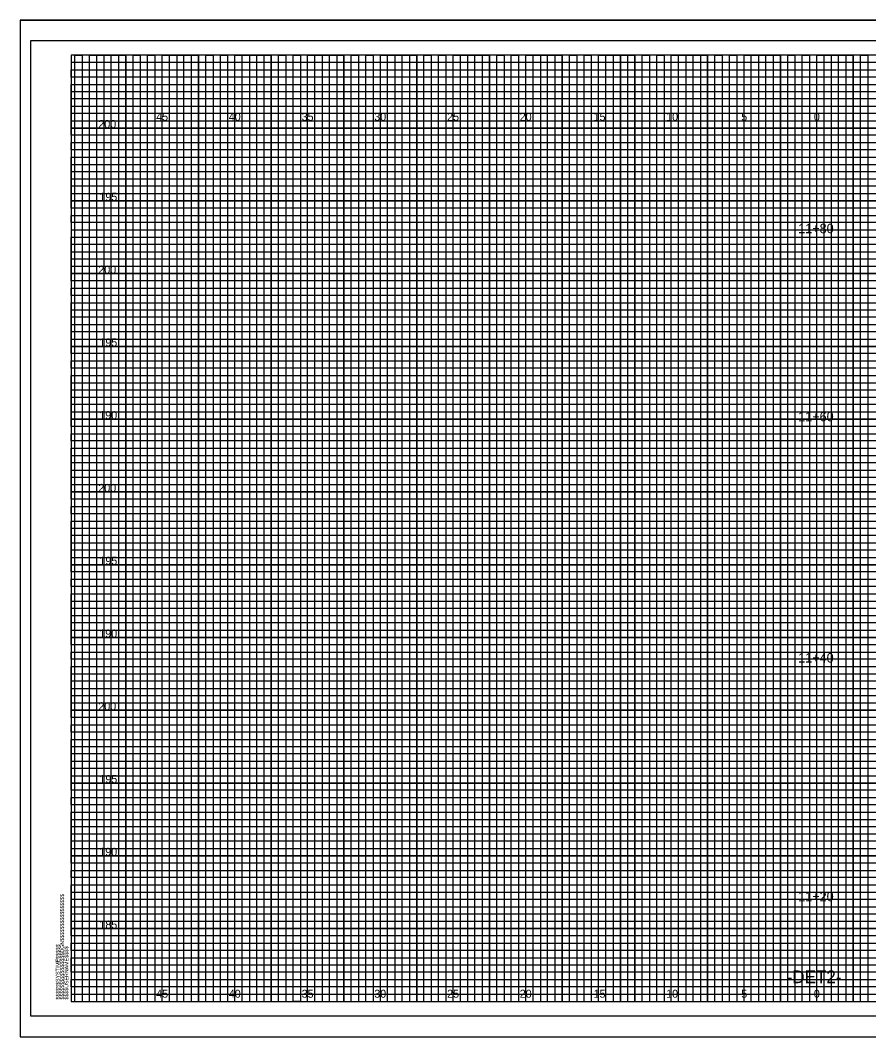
# Model space of a CAD drawing. Extents: x -4 to 103, y -2 to 209.
# Drawn here: x -3.5 to 54.8, y 68.4 to 138.2 of the extents above; entities that cross this region are included whole.
import ezdxf

# ---------------------------------------------------------------- set-up
doc = ezdxf.new("R2010")
doc.units = 0
for name, color, linetype in [('Exist XS Ground Line', 7, 'Continuous'), ('Old_Level_10', 7, 'Continuous'), ('Old_Level_3', 7, 'Continuous'), ('Old_Level_5', 7, 'Continuous'), ('Old_Level_8', 7, 'Continuous'), ('Prop XS Dump Level', 7, 'Continuous'), ('Prop XS Elevation Labels', 7, 'Continuous'), ('Prop XS EOT Tick Mark', 7, 'Continuous'), ('Prop XS Finish Grade', 7, 'Continuous'), ('Prop XS Hydro Elevations', 7, 'Continuous'), ('Prop XS Label Text', 7, 'Continuous')]:
    doc.layers.add(name, color=color, linetype=linetype)

msp = doc.modelspace()

# ---------------------------------------------------------------- linework, layer by layer
at = {"layer": 'Exist XS Ground Line'}
msp.add_lwpolyline([(103, 136.825), (-2.8, 136.825), (-2.8, 69.825), (103, 69.825)], close=True, dxfattribs=at)
at = {"layer": 'Old_Level_10'}
for p, q in [((1.25, 70.825), (1.25, 135.825)), ((3.75, 70.825), (3.75, 135.825)), ((6.25, 70.825), (6.25, 135.825)), ((8.75, 70.825), (8.75, 135.825)), ((11.25, 70.825), (11.25, 135.825)), ((13.75, 70.825), (13.75, 135.825)), ((16.25, 70.825), (16.25, 135.825)), ((18.75, 70.825), (18.75, 135.825)), ((21.25, 70.825), (21.25, 135.825)), ((23.75, 70.825), (23.75, 135.825)), ((26.25, 70.825), (26.25, 135.825)), ((28.75, 70.825), (28.75, 135.825)), ((31.25, 70.825), (31.25, 135.825)), ((33.75, 70.825), (33.75, 135.825)), ((36.25, 70.825), (36.25, 135.825)), ((38.75, 70.825), (38.75, 135.825)), ((41.25, 70.825), (41.25, 135.825)), ((43.75, 70.825), (43.75, 135.825)), ((46.25, 70.825), (46.25, 135.825)), ((48.75, 70.825), (48.75, 135.825)), ((51.25, 70.825), (51.25, 135.825)), ((53.75, 70.825), (53.75, 135.825)), ((0, 133.325), (74.25, 133.325)), ((0, 130.825), (102.5, 130.825)), ((0, 128.325), (102.5, 128.325)), ((0, 125.825), (102.5, 125.825)), ((0, 123.325), (102.5, 123.325)), ((0, 120.825), (102.5, 120.825)), ((0, 118.325), (102.5, 118.325)), ((0, 115.825), (102.5, 115.825)), ((0, 113.325), (102.5, 113.325)), ((0, 110.825), (102.5, 110.825)), ((0, 108.325), (102.5, 108.325)), ((0, 105.825), (102.5, 105.825)), ((0, 103.325), (102.5, 103.325)), ((0, 100.825), (102.5, 100.825)), ((0, 98.325), (102.5, 98.325)), ((0, 95.825), (102.5, 95.825)), ((0, 93.325), (102.5, 93.325)), ((0, 90.825), (102.5, 90.825)), ((0, 88.325), (102.5, 88.325)), ((0, 85.825), (102.5, 85.825)), ((0, 83.325), (102.5, 83.325)), ((0, 80.825), (102.5, 80.825)), ((0, 78.325), (102.5, 78.325)), ((0, 75.825), (102.5, 75.825)), ((0, 73.325), (102.5, 73.325))]:
    msp.add_line(p, q, dxfattribs=at)
at = {"layer": 'Old_Level_3'}
for p, q in [((-3.5, 138.225), (103.4, 138.225)), ((-3.5, 138.225), (-3.5, 68.4)), ((-3.5, 68.4), (103.4, 68.4))]:
    msp.add_line(p, q, dxfattribs=at)
at = {"layer": 'Old_Level_5'}
msp.add_lwpolyline([(103.4, 138.225), (-3.5, 138.225), (-3.5, 68.4), (103.4, 68.4)], close=True, dxfattribs=at)
at = {"layer": 'Old_Level_8'}
for points in [[(1.25, 70.825), (1.25, 135.825), (3.75, 135.825), (3.75, 70.825), (6.25, 70.825), (6.25, 135.825), (8.75, 135.825), (8.75, 70.825), (11.25, 70.825), (11.25, 135.825), (13.75, 135.825), (13.75, 70.825), (16.25, 70.825), (16.25, 135.825), (18.75, 135.825), (18.75, 70.825), (21.25, 70.825), (21.25, 135.825), (23.75, 135.825), (23.75, 70.825), (26.25, 70.825), (26.25, 135.825), (28.75, 135.825), (28.75, 70.825), (31.25, 70.825), (31.25, 135.825), (33.75, 135.825), (33.75, 70.825), (36.25, 70.825), (36.25, 135.825), (38.75, 135.825), (38.75, 70.825), (41.25, 70.825), (41.25, 135.825), (43.75, 135.825), (43.75, 70.825), (46.25, 70.825), (46.25, 135.825), (48.75, 135.825), (48.75, 70.825), (51.25, 70.825), (51.25, 135.825), (53.75, 135.825), (53.75, 70.825)], [(102.5, 130.825), (0, 130.825), (0, 133.325), (74.25, 133.325)], [(102.5, 125.825), (0, 125.825), (0, 128.325), (102.5, 128.325)], [(102.5, 120.825), (0, 120.825), (0, 123.325), (102.5, 123.325)], [(102.5, 115.825), (0, 115.825), (0, 118.325), (102.5, 118.325)], [(102.5, 110.825), (0, 110.825), (0, 113.325), (102.5, 113.325)], [(102.5, 105.825), (0, 105.825), (0, 108.325), (102.5, 108.325)], [(102.5, 100.825), (0, 100.825), (0, 103.325), (102.5, 103.325)], [(102.5, 95.825), (0, 95.825), (0, 98.325), (102.5, 98.325)], [(102.5, 90.825), (0, 90.825), (0, 93.325), (102.5, 93.325)], [(102.5, 85.825), (0, 85.825), (0, 88.325), (102.5, 88.325)], [(102.5, 80.825), (0, 80.825), (0, 83.325), (102.5, 83.325)], [(102.5, 75.825), (0, 75.825), (0, 78.325), (102.5, 78.325)], [(0, 73.325), (102.5, 73.325)]]:
    msp.add_lwpolyline(points, dxfattribs=at)
at = {"layer": 'Prop XS Dump Level'}
msp.add_lwpolyline([(102.5, 135.825), (0, 135.825), (0, 70.825), (102.5, 70.825)], close=True, dxfattribs=at)
at = {"layer": 'Prop XS Finish Grade'}
for points in [[(0.25, 70.825), (0.25, 135.825), (0.75, 135.825), (0.75, 70.825), (1.75, 70.825), (1.75, 135.825), (2.25, 135.825), (2.25, 70.825), (2.75, 70.825), (2.75, 135.825), (3.25, 135.825), (3.25, 70.825), (4.25, 70.825), (4.25, 135.825), (4.75, 135.825), (4.75, 70.825), (5.25, 70.825), (5.25, 135.825), (5.75, 135.825), (5.75, 70.825), (6.75, 70.825), (6.75, 135.825), (7.25, 135.825), (7.25, 70.825), (7.75, 70.825), (7.75, 135.825), (8.25, 135.825), (8.25, 70.825), (9.25, 70.825), (9.25, 135.825), (9.75, 135.825), (9.75, 70.825), (10.25, 70.825), (10.25, 135.825), (10.75, 135.825), (10.75, 70.825), (11.75, 70.825), (11.75, 135.825), (12.25, 135.825), (12.25, 70.825), (12.75, 70.825), (12.75, 135.825), (13.25, 135.825), (13.25, 70.825), (14.25, 70.825), (14.25, 135.825), (14.75, 135.825), (14.75, 70.825), (15.75, 70.825), (15.25, 70.825), (15.25, 135.825), (15.75, 135.825), (15.75, 70.825), (16.75, 70.825), (16.75, 135.825), (17.25, 135.825), (17.25, 70.825), (17.75, 70.825), (17.75, 135.825), (18.25, 135.825), (18.25, 70.825), (19.25, 70.825), (19.25, 135.825), (19.75, 135.825), (19.75, 70.825), (20.25, 70.825), (20.25, 135.825), (20.75, 135.825), (20.75, 70.825), (21.75, 70.825), (21.75, 135.825), (22.25, 135.825), (22.25, 70.825), (22.75, 70.825), (22.75, 135.825), (23.25, 135.825), (23.25, 70.825), (24.25, 70.825), (24.25, 135.825), (24.75, 135.825), (24.75, 70.825), (25.25, 70.825), (25.25, 135.825), (25.75, 135.825), (25.75, 70.825), (26.75, 70.825), (26.75, 135.825), (27.25, 135.825), (27.25, 70.825), (27.75, 70.825), (27.75, 135.825), (28.25, 135.825), (28.25, 70.825), (29.25, 70.825), (29.25, 135.825), (29.75, 135.825), (29.75, 70.825), (30.25, 70.825), (30.25, 135.825), (30.75, 135.825), (30.75, 70.825)], [(30.75, 70.825), (31.75, 70.825), (31.75, 135.825), (32.25, 135.825), (32.25, 70.825), (32.75, 70.825), (32.75, 135.825), (33.25, 135.825), (33.25, 70.825), (34.25, 70.825), (34.25, 135.825), (34.75, 135.825), (34.75, 70.825), (35.25, 70.825), (35.25, 135.825), (35.75, 135.825), (35.75, 70.825), (36.75, 70.825), (36.75, 135.825), (37.25, 135.825), (37.25, 70.825), (37.75, 70.825), (37.75, 135.825), (37.75, 70.825)], [(38.25, 135.825), (38.25, 70.825), (39.25, 70.825), (39.25, 135.825), (39.75, 135.825), (39.75, 70.825), (40.25, 70.825), (40.25, 135.825), (40.75, 135.825), (40.75, 70.825), (41.75, 70.825), (41.75, 135.825), (42.25, 135.825), (42.25, 70.825), (42.75, 70.825), (42.75, 135.825), (43.25, 135.825), (43.25, 70.825), (43.75, 70.825), (44.25, 70.825), (44.25, 135.825), (44.75, 135.825), (44.75, 70.825), (45.25, 70.825), (45.25, 135.825), (45.75, 135.825), (45.75, 70.825), (46.75, 70.825), (46.75, 135.825), (47.25, 135.825), (47.25, 70.825), (47.75, 70.825), (47.75, 135.825), (48.25, 135.825), (48.25, 70.825), (49.25, 70.825), (49.25, 135.825), (49.75, 135.825), (49.75, 70.825), (50.25, 70.825), (50.25, 135.825), (50.75, 135.825), (50.75, 70.825), (51.75, 70.825), (51.75, 135.825), (52.25, 135.825), (52.25, 70.825), (52.75, 70.825), (52.75, 135.825), (53.25, 135.825), (53.25, 70.825), (54.25, 70.825), (54.25, 135.825), (54.75, 135.825), (54.75, 70.825), (55.25, 70.825)], [(0, 132.825), (0, 133.825), (74.25, 133.825), (74.25, 134.325), (0, 134.325), (0, 134.825), (74.25, 134.825), (74.25, 135.325), (0, 135.325)], [(102.5, 132.825), (0, 132.825)], [(102.5, 131.825), (0, 131.825), (0, 132.325), (102.5, 132.325)], [(102.5, 130.325), (0, 130.325), (0, 131.325), (102.5, 131.325)], [(102.5, 129.325), (0, 129.325), (0, 129.825), (102.5, 129.825)], [(102.5, 127.825), (0, 127.825), (0, 128.825), (102.5, 128.825)], [(102.5, 126.825), (0, 126.825), (0, 127.325), (102.5, 127.325)], [(102.5, 125.325), (0, 125.325), (0, 126.325), (102.5, 126.325)], [(102.5, 124.325), (0, 124.325), (0, 124.825), (102.5, 124.825)], [(0, 123.825), (102.5, 123.825)], [(102.5, 122.825), (0, 122.825)], [(102.5, 121.825), (0, 121.825), (0, 122.325), (102.5, 122.325)], [(102.5, 120.325), (0, 120.325), (0, 121.325), (102.5, 121.325)], [(102.5, 119.325), (0, 119.325), (0, 119.825), (102.5, 119.825)], [(102.5, 117.825), (0, 117.825), (0, 118.825), (102.5, 118.825)], [(102.5, 116.825), (0, 116.825), (0, 117.325), (102.5, 117.325)], [(102.5, 115.325), (0, 115.325), (0, 116.325), (102.5, 116.325)], [(102.5, 114.325), (0, 114.325), (0, 114.825), (102.5, 114.825)], [(102.5, 112.825), (0, 112.825), (0, 113.825), (102.5, 113.825)], [(102.5, 111.825), (0, 111.825), (0, 112.325), (102.5, 112.325)], [(102.5, 110.325), (0, 110.325), (0, 111.325), (102.5, 111.325)], [(102.5, 109.325), (0, 109.325), (0, 109.825), (102.5, 109.825)], [(102.5, 107.825), (0, 107.825), (0, 108.825), (102.5, 108.825)], [(102.5, 106.825), (0, 106.825), (0, 107.325), (102.5, 107.325)], [(102.5, 105.325), (0, 105.325), (0, 106.325), (102.5, 106.325)], [(102.5, 104.325), (0, 104.325), (0, 104.825), (102.5, 104.825)], [(102.5, 102.825), (0, 102.825), (0, 103.825), (102.5, 103.825)], [(102.5, 101.825), (0, 101.825), (0, 102.325)], [(0, 102.325), (102.5, 102.325)], [(102.5, 100.325), (0, 100.325), (0, 101.325), (102.5, 101.325)], [(102.5, 99.325), (0, 99.325), (0, 99.825), (102.5, 99.825)], [(102.5, 97.825), (0, 97.825), (0, 98.825), (102.5, 98.825)], [(102.5, 96.825), (0, 96.825), (0, 97.325), (102.5, 97.325)], [(102.5, 95.325), (0, 95.325), (0, 96.325), (102.5, 96.325)], [(102.5, 94.325), (0, 94.325), (0, 94.825), (102.5, 94.825)], [(102.5, 92.825), (0, 92.825), (0, 93.825), (102.5, 93.825)], [(102.5, 91.825), (0, 91.825), (0, 92.325), (102.5, 92.325)], [(102.5, 90.325), (0, 90.325), (0, 91.325), (102.5, 91.325)], [(102.5, 89.325), (0, 89.325), (0, 89.825), (102.5, 89.825)], [(102.5, 87.825), (0, 87.825), (0, 88.825), (102.5, 88.825)], [(102.5, 86.825), (0, 86.825), (0, 87.325), (102.5, 87.325)], [(102.5, 85.325), (0, 85.325), (0, 86.325), (102.5, 86.325)], [(102.5, 84.325), (0, 84.325), (0, 84.825), (102.5, 84.825)], [(102.5, 82.825), (0, 82.825), (0, 83.825), (102.5, 83.825)], [(102.5, 81.825), (0, 81.825), (0, 82.325), (102.5, 82.325)], [(102.5, 80.325), (0, 80.325), (0, 81.325), (102.5, 81.325)], [(102.5, 79.325), (0, 79.325), (0, 79.825), (102.5, 79.825)], [(102.5, 77.825), (0, 77.825), (0, 78.825), (102.5, 78.825)], [(102.5, 76.825), (0, 76.825), (0, 77.325), (102.5, 77.325)], [(102.5, 75.325), (0, 75.325), (0, 76.325), (102.5, 76.325)], [(102.5, 74.325), (0, 74.325), (0, 74.825), (102.5, 74.825)], [(102.5, 72.825), (0, 72.825), (0, 73.825), (102.5, 73.825)], [(102.5, 71.825), (0, 71.825), (0, 72.325), (102.5, 72.325)], [(0, 71.325), (102.5, 71.325)]]:
    msp.add_lwpolyline(points, dxfattribs=at)

# ---------------------------------------------------------------- texts
at = {"layer": 'Old_Level_8'}
msp.add_text('040397', height=0.0025, rotation=90, dxfattribs=at).set_placement((-0.0007, 135.8114))
at = {"layer": 'Prop XS Dump Level'}
for s, p in [('$$$$$$$$$$$$$$$$DGN$$$$$$$$$$$$$$$$', (-0.5, 70.95)), ('$$$$$$SYSTIME$$$$$', (-0.7973, 70.9497)), ('$$$$USERNAME$$$$', (-0.2, 70.95))]:
    msp.add_text(s, height=0.2625, rotation=90, dxfattribs=at).set_placement(p)
at = {"layer": 'Prop XS Elevation Labels'}
for s, p in [('45', (5.8399, 131.325)), ('40', (10.8313, 131.325)), ('35', (15.8399, 131.325)), ('30', (20.8313, 131.325)), ('25', (25.8399, 131.325)), ('20', (30.8313, 131.325)), ('15', (35.9058, 131.325)), ('10', (40.8971, 131.325)), ('5', (46.0574, 131.325)), ('0', (51.0488, 131.325)), ('0', (51.0488, 131.325)), ('45', (5.8399, 71.075)), ('40', (10.8313, 71.075)), ('35', (15.8399, 71.075)), ('30', (20.8313, 71.075)), ('25', (25.8399, 71.075)), ('20', (30.8313, 71.075)), ('15', (35.9058, 71.075)), ('10', (40.8971, 71.075)), ('5', (46.0574, 71.075)), ('0', (51.0488, 71.075)), ('0', (51.0488, 71.075))]:
    msp.add_text(s, height=0.55, dxfattribs=at).set_placement(p)
at = {"layer": 'Prop XS EOT Tick Mark'}
msp.add_text('-DET2-', height=0.875, dxfattribs=at).set_placement((49.1786, 72.075))
at = {"layer": 'Prop XS Hydro Elevations'}
for s, p in [('11+80', (49.9712, 123.6013)), ('11+60', (49.9712, 110.6745)), ('11+40', (49.9712, 94.1047)), ('11+20', (49.9712, 77.7065))]:
    msp.add_text(s, height=0.65, dxfattribs=at).set_placement(p)
at = {"layer": 'Prop XS Label Text'}
for s, p in [('200', (1.8638, 130.825)), ('195', (1.9383, 125.825)), ('200', (1.8638, 120.825)), ('195', (1.9383, 115.825)), ('190', (1.9296, 110.825)), ('200', (1.8638, 105.825)), ('195', (1.9383, 100.825)), ('190', (1.9296, 95.825)), ('200', (1.8638, 90.825)), ('195', (1.9383, 85.825)), ('190', (1.9296, 80.825)), ('185', (1.9383, 75.825))]:
    msp.add_text(s, height=0.55, dxfattribs=at).set_placement(p)

doc.saveas('drawing.dxf')
